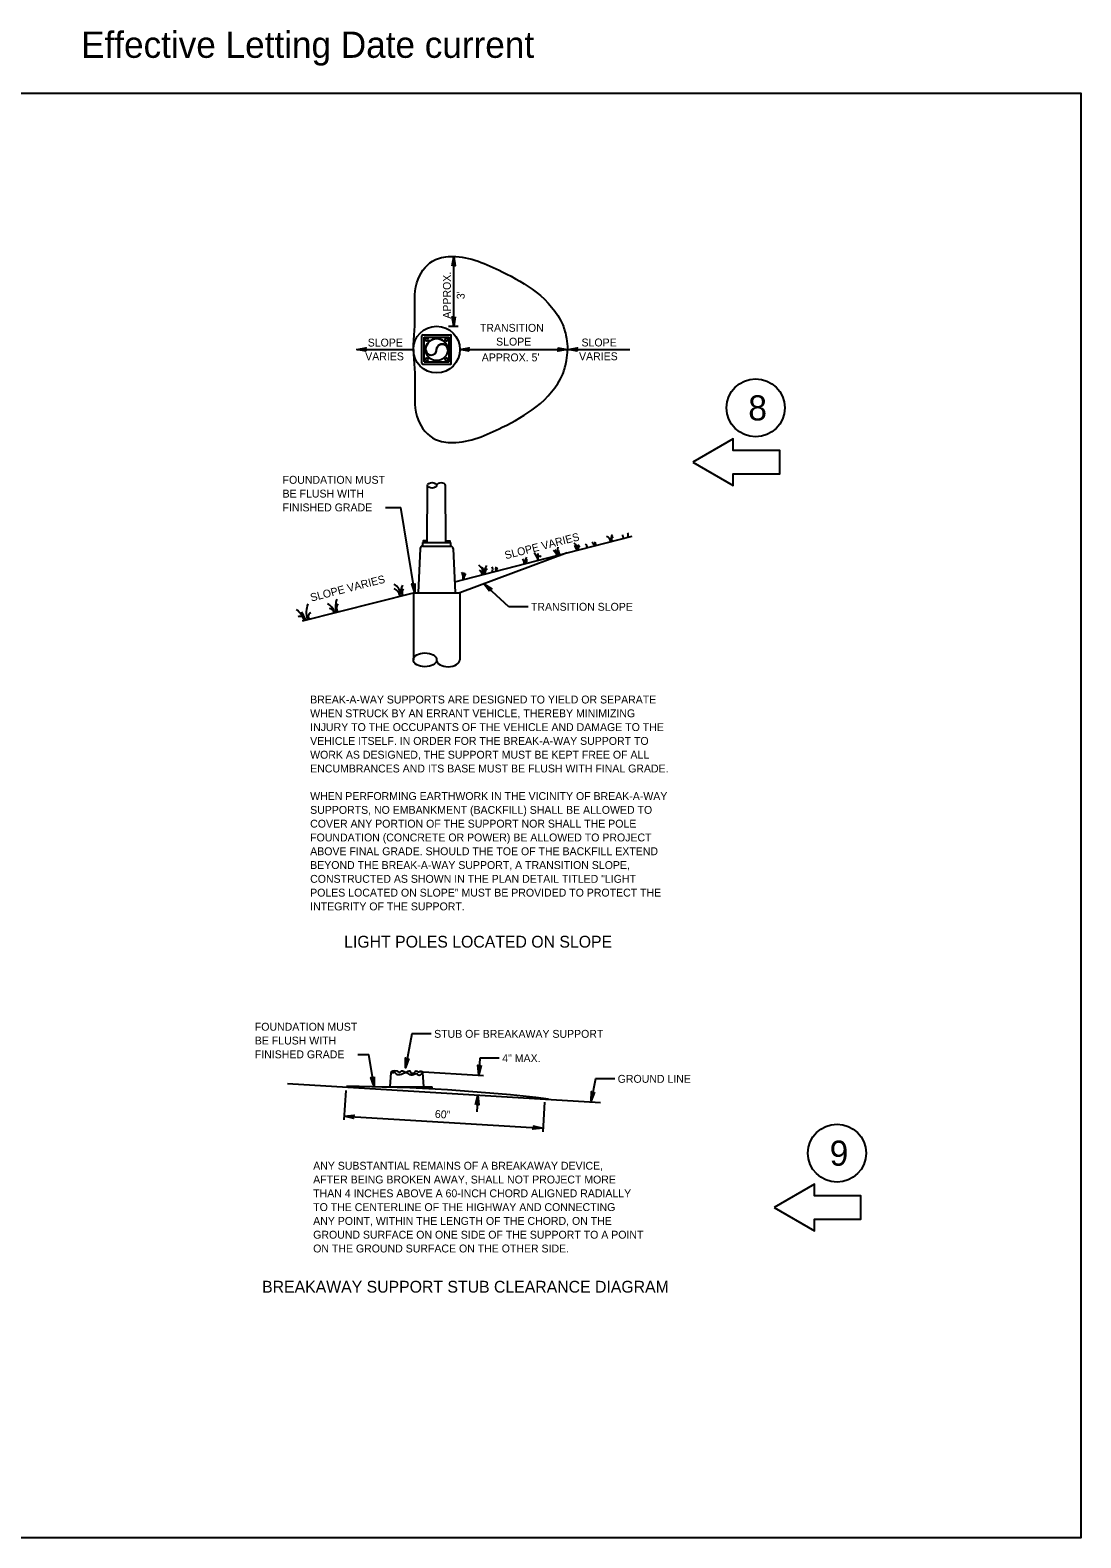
# Model space of a CAD drawing. Extents: x 99981 to 128681, y 99783 to 102182.
# Drawn here: x 116881 to 118481, y 99887 to 102182 of the extents above; entities that cross this region are included whole.
import ezdxf

# ---------------------------------------------------------------- set-up
doc = ezdxf.new("R2010")
doc.units = 0
for name, color, linetype in [('Default', 7, 'Continuous'), ('Level 1', 7, 'Continuous'), ('Level 7', 7, 'Continuous'), ('RD Lighting', 7, 'Continuous'), ('RD Standard Plans Active', 7, 'Continuous')]:
    doc.layers.add(name, color=color, linetype=linetype)

msp = doc.modelspace()

# ---------------------------------------------------------------- linework, layer by layer
at = {"layer": 'Default'}
msp.add_lwpolyline([(115281.4, 102086.3), (118481.1, 102086.3), (118481.1, 99886.7), (115281.4, 99886.7)], close=True, dxfattribs=at)
at = {"layer": 'Level 1'}
for p, q in [((117526.2, 101731.6), (117526.2, 101837.2)), ((117477.8, 101675), (117477.8, 101716.9)), ((117479.2, 101718.3), (117521.1, 101718.3)), ((117481.3, 101714.8), (117519, 101714.8)), ((117481.3, 101677.1), (117481.3, 101714.8)), ((117518.3, 101731.6), (117532.7, 101731.6)), ((117519, 101677.1), (117519, 101714.8)), ((117522.5, 101675), (117522.5, 101716.9)), ((117378.9, 101695.9), (117464.7, 101695.9)), ((117483.4, 101695.9), (117483.4, 101695.8)), ((117483.4, 101695.8), (117484, 101693.2)), ((117535.6, 101695.9), (117699, 101695.9)), ((117700.5, 101695.9), (117794.2, 101695.9)), ((117479.2, 101673.6), (117521.1, 101673.6)), ((117481.3, 101677.1), (117519, 101677.1)), ((117486, 101402.3), (117486.4, 101489.1)), ((117514.4, 101402.3), (117513.9, 101489.1)), ((117422.5, 101455.5), (117445.8, 101455.5)), ((117466.9, 101325.6), (117445.8, 101455.5)), ((117475.2, 101393.2), (117471.8, 101325.6)), ((117478.7, 101402.3), (117521.6, 101402.3)), ((117478.7, 101402.3), (117478.7, 101396.6)), ((117478.7, 101396.6), (117521.6, 101396.6)), ((117521.6, 101396.6), (117521.6, 101402.3)), ((117525.2, 101393.2), (117528.5, 101325.6)), ((117698.8, 101386.2), (117797.7, 101411.6)), ((117527.7, 101342.2), (117698.9, 101386.2)), ((117698.8, 101386.2), (117535.6, 101325.6)), ((117296, 101282.7), (117464.7, 101325.6)), ((117464.7, 101325.6), (117535.6, 101325.6)), ((117464.7, 101325.6), (117464.7, 101223.5)), ((117535.6, 101325.6), (117535.6, 101223.5)), ((117609.9, 101304.2), (117572.1, 101339.2)), ((117639.3, 101304.2), (117609.9, 101304.2)), ((117462.4, 100654), (117452.6, 100602.5)), ((117491.9, 100654), (117462.4, 100654)), ((117380.2, 100622.8), (117396.8, 100622.8)), ((117404.8, 100573.4), (117396.8, 100622.8)), ((117566.1, 100617), (117564.6, 100591.2)), ((117595.6, 100617), (117566.1, 100617)), ((117429.5, 100573.3), (117430.9, 100595.2)), ((117471.7, 100596.8), (117571.4, 100590.8)), ((117480.8, 100573.3), (117479.4, 100595.2)), ((117273, 100578.3), (117749.8, 100549.6)), ((117361.8, 100568), (117359.1, 100523)), ((117416.7, 100573.3), (117493.6, 100573.3)), ((117493.6, 100569.8), (117493.6, 100573.3)), ((117742, 100585.5), (117735.5, 100552)), ((117771.4, 100585.5), (117742, 100585.5)), ((117562.8, 100560.9), (117561.2, 100535.2)), ((117664.5, 100549.8), (117661.8, 100504.8)), ((117359.4, 100528.5), (117661.8, 100510.3))]:
    msp.add_line(p, q, dxfattribs=at)
for points in [[(117523.9, 101823.1), (117526.2, 101837.2), (117528.6, 101823.1), (117526.2, 101825.3)], [(117528.6, 101745.7), (117526.2, 101731.6), (117523.9, 101745.7), (117526.2, 101743.5)], [(117393, 101693.5), (117378.9, 101695.9), (117393, 101698.3), (117390.8, 101695.9)], [(117549.7, 101693.5), (117535.6, 101695.9), (117549.7, 101698.3), (117547.5, 101695.9)], [(117684.9, 101698.3), (117699, 101695.9), (117684.9, 101693.5), (117687.1, 101695.9)], [(117714.6, 101693.5), (117700.5, 101695.9), (117714.6, 101698.3), (117712.4, 101695.9)], [(117479.9, 101402.3), (117484.6, 101402.3), (117484.6, 101404.5), (117479.9, 101404.5)], [(117520.4, 101402.3), (117515.7, 101402.3), (117515.7, 101404.5), (117520.4, 101404.5)], [(117467, 101339.9), (117466.9, 101325.6), (117462.3, 101339.2), (117465, 101337.4)], [(117580.8, 101327.9), (117572.1, 101339.2), (117584.1, 101331.4), (117580.8, 101331.1)], [(117740.5, 100565.4), (117735.5, 100552), (117735.8, 100566.3), (117737.7, 100563.7)]]:
    msp.add_lwpolyline(points, close=True, dxfattribs=at)
msp.add_lwpolyline([(117484, 101693.2), (117485.4, 101690.6), (117487.1, 101688.9), (117488.9, 101688), (117491.5, 101687.5), (117493.5, 101687.7), (117495.9, 101688.5), (117497.4, 101689.6), (117499.2, 101691.8), (117500.1, 101693.9), (117500, 101695.7), (117500.7, 101698.8), (117501.7, 101700.7), (117503.4, 101702.5), (117505.3, 101703.7), (117507.7, 101704.2), (117509.6, 101704.2), (117511.5, 101703.8), (117513.3, 101702.9), (117515.2, 101701.3), (117516.1, 101699.6), (117516.7, 101697.8), (117516.8, 101698.7), (117515.6, 101702.3), (117514.5, 101705), (117512.3, 101707.7), (117509.2, 101710.1), (117505.7, 101711.7), (117502.5, 101712.5), (117497.6, 101712.5), (117494.1, 101711.5), (117490.7, 101709.8), (117487.7, 101707.3), (117485, 101702.7), (117483.9, 101699.3), (117483.4, 101695.9)], dxfattribs=at)
for centre, radius in [((117500.2, 101695.9), 35.5), ((117485.2, 101710.6), 2.01), ((117500.2, 101695.9), 16.8), ((117515.1, 101710.6), 2.01), ((117485.2, 101681.3), 2.01), ((117515.1, 101681.3), 2.01)]:
    msp.add_circle(centre, radius, dxfattribs=at)
for centre, radius, start, end in [((117479.2, 101716.9), 1.42, 90, 180), ((117521.1, 101716.9), 1.42, 0, 90), ((117491.8, 101695.9), 8.38, 181.1458, 359.8277), ((117508.5, 101695.9), 8.38, 359.0325, 180.1514), ((117479.2, 101675), 1.42, 180, 270), ((117521.1, 101675), 1.42, 270, 360), ((117784.5, 101412.5), 7.49, 348.7394, 29.8805), ((117478.7, 101393), 3.55, 90, 177.1601), ((117521.6, 101393), 3.55, 2.8557, 90), ((117701.8, 101391.6), 17.4, 168.5045, 208.2233), ((117699, 101388.3), 16.7, 11.3155, 49.8545), ((117665.2, 101373), 51.3, 19.1988, 28.7261), ((117721.9, 101394.5), 6.54, 142.3124, 210.838), ((117720, 101392.9), 4.33, 117.3322, 210.777), ((117722.5, 101393.5), 7.15, 5.4835, 55.0489), ((117722.9, 101388.5), 19.8, 27.5399, 44.5961), ((117745.8, 101402.2), 4.59, 166.3321, 233.2777), ((117756.9, 101403.1), 8.18, 3.8739, 74.9934), ((117774.6, 101407.2), 9.15, 134.9356, 199.3376), ((117770.9, 101406.5), 4.55, 115.2867, 205.2867), ((117790.3, 101413.4), 7.1, 178.2251, 215.3457), ((117626.6, 101371.3), 6.89, 345.0313, 53.8835), ((117660.8, 101369.5), 26.2, 156.5805, 178.9171), ((117661.3, 101368.1), 25.1, 160.4896, 173.6898), ((117633.6, 101371), 21.4, 12.4259, 46.0534), ((117686.7, 101383.4), 32.7, 176.2233, 193.7374), ((117657.3, 101378), 3.08, 50.8036, 219.1964), ((117659, 101369.3), 28.1, 27.9183, 46.876), ((117663.8, 101376.9), 22.2, 15.7793, 39.8603), ((117696.5, 101389.9), 10.9, 180.2258, 216.7945), ((117528.3, 101348.6), 12.4, 346.9392, 40.0693), ((117550.3, 101350.8), 9.95, 144.9118, 205.1417), ((117552.5, 101346.8), 10.8, 135.7299, 185.7737), ((117556.5, 101354.7), 15, 357.1256, 57.4025), ((117560.7, 101352.3), 9.08, 359.5974, 58.3522), ((117563.3, 101356.3), 9.29, 347.9198, 65.1476), ((117587.3, 101357.5), 14.5, 139.5115, 194.2521), ((117581.5, 101355.3), 7.8, 123.7866, 183.2713), ((117575.7, 101360.8), 9.82, 339.7628, 26.5042), ((117595.7, 101361.6), 5.71, 145.9681, 205.0796), ((117596.2, 101360.2), 4.78, 136.7996, 182.14), ((117423.5, 101320), 22.4, 5.7771, 57.3172), ((117428.2, 101316.7), 16.9, 14.7005, 64.0303), ((117459.8, 101328.8), 14, 144.5318, 205.0793), ((117455.8, 101325.7), 8.21, 138.4572, 205.2826), ((117257.7, 101267.1), 44.2, 22.8572, 48.6096), ((117340.4, 101294.8), 38.7, 159.1068, 194.7019), ((117323.6, 101289), 22.4, 18.3814, 62.2849), ((117336.1, 101294.2), 7.64, 8.8926, 81.324), ((117388.1, 101303.3), 41.9, 162.616, 189.9967), ((117357.5, 101302), 9.74, 140.5529, 212.9541), ((117292.3, 101284), 5.57, 357.1521, 119.7071), ((117260.4, 101271.5), 42, 17.8044, 35.4218), ((117310.6, 101289.5), 6.03, 108.2858, 212.2696), ((117338.5, 97728), 2846.2, 83.3057, 89.5058)]:
    msp.add_arc(centre, radius, start, end, dxfattribs=at)
for centre, major_axis, ratio in [((117493.3, 101489.1), (6.86, 0), 0.617037), ((117482.4, 101223.5), (17.7, 0), 0.596872)]:
    msp.add_ellipse(centre, major_axis=major_axis, ratio=ratio, dxfattribs=at)
for centre, major_axis, ratio, start_param, end_param in [((117507, 101488.7), (6.86, 0), 0.617037, 0.080151, 3.060837), ((117517.8, 101223.6), (17.7, 0), 0.596872, 3.156201, 6.283491)]:
    msp.add_ellipse(centre, major_axis=major_axis, ratio=ratio, start_param=start_param, end_param=end_param, dxfattribs=at)
for points in [[(117464.7, 101695.9), (117467.1, 101754), (117471.9, 101803.2), (117498.4, 101832.9), (117524.3, 101837.6), (117600, 101814.3), (117651.9, 101783.1), (117692.1, 101733.3), (117697.9, 101712.7), (117699.5, 101696.2)], [(117464.7, 101695.9), (117467.1, 101637.9), (117471.9, 101588.7), (117498.4, 101559), (117524.3, 101554.2), (117600, 101577.5), (117651.9, 101608.8), (117692.1, 101658.6), (117697.9, 101679.2), (117699.5, 101695.6)], [(117479.4, 100595.1), (117472.2, 100591), (117471.2, 100592.6), (117462.9, 100591), (117456.9, 100593.5), (117453.8, 100594.5), (117443.9, 100591.6), (117437.9, 100593.5), (117435.8, 100595.1), (117433.2, 100594.6), (117431.3, 100595.5), (117439.6, 100597.5), (117444.4, 100595.6), (117446.6, 100597.7), (117453.7, 100595.7), (117459.3, 100597.5), (117461.3, 100594.7), (117467, 100595.6), (117468.6, 100597.6), (117471.7, 100596), (117475.1, 100597), (117479.3, 100595.2), (117477.5, 100594.1)]]:
    msp.add_spline(points, degree=3, dxfattribs=at)
at = {"layer": 'Level 7'}
for points in [[(117457.9, 100616.6), (117452.6, 100602.5), (117452.9, 100617.6), (117454.9, 100614.8)], [(117404.9, 100588.5), (117404.8, 100573.4), (117399.9, 100587.7), (117402.8, 100585.8)], [(117568, 100606), (117564.6, 100591.2), (117563, 100606.3), (117565.3, 100603.8)], [(117559.4, 100546.2), (117562.8, 100560.9), (117564.4, 100545.9), (117562, 100548.3)], [(117374.1, 100525.1), (117359.4, 100528.5), (117374.4, 100530.1), (117372, 100527.8)], [(117647, 100513.8), (117661.8, 100510.3), (117646.7, 100508.7), (117649.2, 100511.1)]]:
    msp.add_lwpolyline(points, close=True, dxfattribs=at)
at = {"layer": 'RD Lighting'}
for points in [[(117890.1, 101524.3), (117951.5, 101488.8), (117951.5, 101506.5), (118022.5, 101506.5), (118022.5, 101542), (117951.5, 101542), (117951.5, 101559.8)], [(118013.9, 100389.6), (118075.4, 100354.1), (118075.4, 100371.9), (118146.3, 100371.9), (118146.3, 100407.4), (118075.4, 100407.4), (118075.4, 100425.1)]]:
    msp.add_lwpolyline(points, close=True, dxfattribs=at)
for centre in [(117985.9, 101607.1), (118109.8, 100472.4)]:
    msp.add_circle(centre, 44.2, dxfattribs=at)

# ---------------------------------------------------------------- texts
at = {"layer": 'Level 1'}
for s, rotation, p in [('APPROX. ', 90, (117521.8, 101742.9)), ("3'", 90, (117542.8, 101772.5)), ('SLOPE VARIES', 14.4122, (117605.4, 101376.5)), ('SLOPE VARIES', 14.4114, (117309.5, 101312.1)), ('60"', 356.561, (117497.2, 100526.2))]:
    msp.add_text(s, height=12, rotation=rotation, dxfattribs=at).set_placement(p)
for s, height, p in [('TRANSITION ', 12, (117566.1, 101722.9)), ('SLOPE', 12, (117590.7, 101701.9)), ('VARIES', 12, (117391.4, 101679.5)), ('SLOPE', 12, (117395.2, 101700.5)), ("APPROX. 5'", 12, (117568.9, 101677.9)), ('VARIES', 12, (117717, 101679.6)), ('SLOPE', 12, (117720.8, 101700.6)), ('FOUNDATION MUST ', 12, (117265.6, 101491.5)), ('BE FLUSH WITH ', 12, (117265.6, 101470.5)), ('FINISHED GRADE ', 12, (117265.6, 101449.5)), (' TRANSITION SLOPE', 12, (117639.3, 101298.2)), ('BREAK-A-WAY SUPPORTS ARE DESIGNED TO YIELD OR SEPARATE', 12, (117307.6, 101157)), ('WHEN STRUCK BY AN ERRANT VEHICLE, THEREBY MINIMIZING', 12, (117307.6, 101136)), ('INJURY TO THE OCCUPANTS OF THE VEHICLE AND DAMAGE TO THE', 12, (117307.6, 101115)), ('VEHICLE ITSELF. IN ORDER FOR THE BREAK-A-WAY SUPPORT TO', 12, (117307.6, 101094)), ('WORK AS DESIGNED, THE SUPPORT MUST BE KEPT FREE OF ALL', 12, (117307.6, 101073)), ('ENCUMBRANCES AND ITS BASE MUST BE FLUSH WITH FINAL GRADE. ', 12, (117307.6, 101052)), ('WHEN PERFORMING EARTHWORK IN THE VICINITY OF BREAK-A-WAY', 12, (117307.6, 101010)), ('SUPPORTS, NO EMBANKMENT (BACKFILL) SHALL BE ALLOWED TO', 12, (117307.6, 100989)), ('COVER ANY PORTION OF THE SUPPORT NOR SHALL THE POLE', 12, (117307.6, 100968)), ('FOUNDATION (CONCRETE OR POWER) BE ALLOWED TO PROJECT', 12, (117307.6, 100947)), ('ABOVE FINAL GRADE. SHOULD THE TOE OF THE BACKFILL EXTEND', 12, (117307.6, 100926)), ('BEYOND THE BREAK-A-WAY SUPPORT, A TRANSITION SLOPE,', 12, (117307.6, 100905)), ('CONSTRUCTED AS SHOWN IN THE PLAN DETAIL TITLED "LIGHT', 12, (117307.6, 100884)), ('POLES LOCATED ON SLOPE" MUST BE PROVIDED TO PROTECT THE', 12, (117307.6, 100863)), ('INTEGRITY OF THE SUPPORT.', 12, (117307.6, 100842)), ('LIGHT POLES LOCATED ON SLOPE', 18, (117359.4, 100785.3)), ('FOUNDATION MUST ', 12, (117223.3, 100658.8)), (' STUB OF BREAKAWAY SUPPORT', 12, (117491.9, 100648)), ('BE FLUSH WITH ', 12, (117223.3, 100637.8)), ('FINISHED GRADE ', 12, (117223.3, 100616.8)), (' 4" MAX.', 12, (117595.6, 100611)), (' GROUND LINE', 12, (117771.4, 100579.5)), ('ANY SUBSTANTIAL REMAINS OF A BREAKAWAY DEVICE,', 12, (117312.2, 100447.2)), ('AFTER BEING BROKEN AWAY, SHALL NOT PROJECT MORE', 12, (117312.2, 100426.2)), ('THAN 4 INCHES ABOVE A 60-INCH CHORD ALIGNED RADIALLY', 12, (117312.2, 100405.2)), ('TO THE CENTERLINE OF THE HIGHWAY AND CONNECTING', 12, (117312.2, 100384.2)), ('ANY POINT, WITHIN THE LENGTH OF THE CHORD, ON THE', 12, (117312.2, 100363.2)), ('GROUND SURFACE ON ONE SIDE OF THE SUPPORT TO A POINT', 12, (117312.2, 100342.2)), ('ON THE GROUND SURFACE ON THE OTHER SIDE.', 12, (117312.2, 100321.2)), ('BREAKAWAY SUPPORT STUB CLEARANCE DIAGRAM', 18, (117234.4, 100260))]:
    msp.add_text(s, height=height, dxfattribs=at).set_placement(p)
at = {"layer": 'RD Lighting'}
for s, p in [('8', (117974.7, 101587.9)), ('9', (118098.6, 100453.2))]:
    msp.add_text(s, height=38.3, dxfattribs=at).set_placement(p)
at = {"layer": 'RD Standard Plans Active'}
msp.add_text('Effective Letting Date current', height=40, dxfattribs=at).set_placement((116958.8, 102140))

doc.saveas('drawing.dxf')
